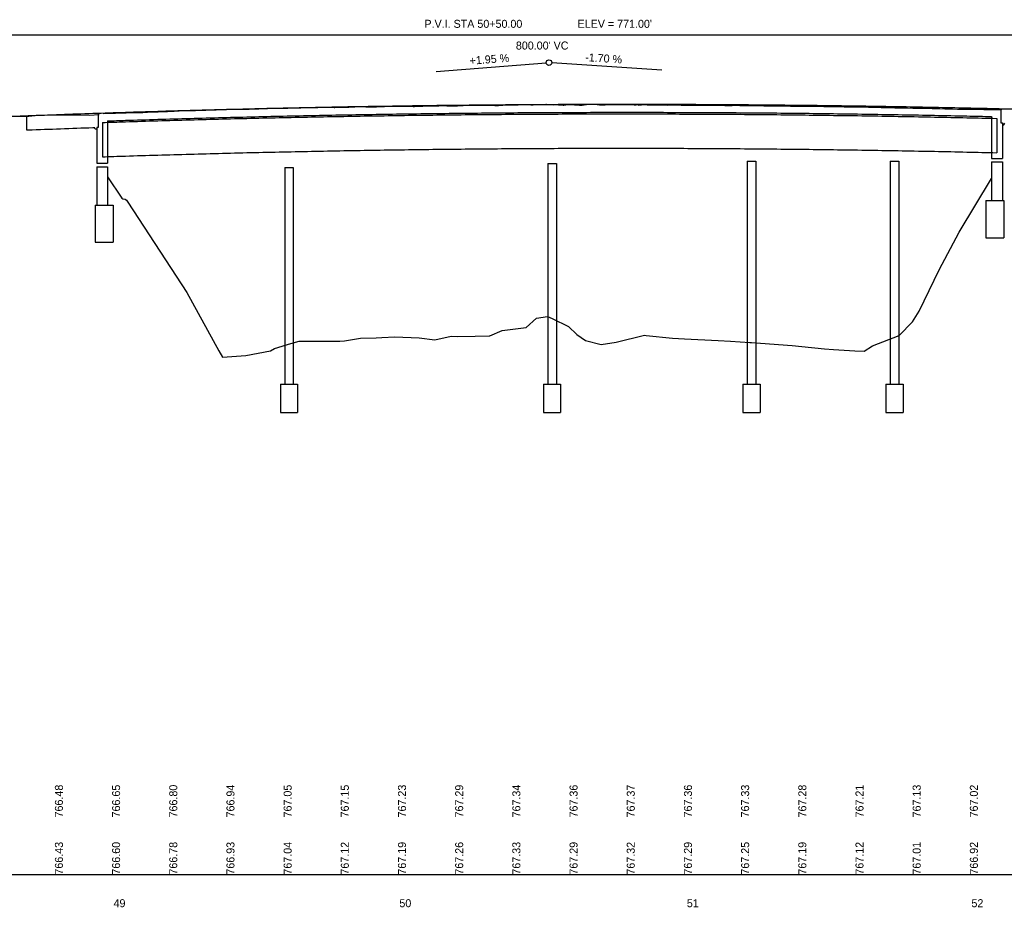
# Model space of a CAD drawing. Extents: x 40 to 3352, y -2509 to 347.
# Drawn here: x 317.3 to 661.7, y -1520 to -1209.6 of the extents above; entities that cross this region are included whole.
import ezdxf

# ---------------------------------------------------------------- set-up
doc = ezdxf.new("R2010")
doc.units = 0
for name, color, linetype in [('BR_P_Gen_Approach_Slab', 7, 'Continuous'), ('BR_P_Slab_Object', 7, 'Continuous'), ('BR_X_Sub_Object', 7, 'Continuous'), ('GK_Cells', 7, 'Continuous'), ('PF_P_Grade_Line', 7, 'Continuous'), ('PF_P_Sta_Elev_Text', 7, 'Continuous'), ('PF_P_Text', 7, 'Continuous'), ('PF_X_Ground_Line', 7, 'Continuous'), ('PF_X_Text', 7, 'Continuous'), ('XS_X_Ground_Line', 7, 'Continuous')]:
    doc.layers.add(name, color=color, linetype=linetype)

msp = doc.modelspace()

# ---------------------------------------------------------------- linework, layer by layer
at = {"layer": 'BR_P_Gen_Approach_Slab'}
for p, q in [((344.73, -1242.25), (344.73, -1247.25)), ((660.49, -1240.69), (660.49, -1245.69)), ((319.73, -1243.15), (319.73, -1248.15)), ((660.49, -1245.69), (660.99, -1245.69)), ((660.99, -1246.35), (661.49, -1246.35)), ((661.49, -1246.35), (661.81, -1245.72)), ((343.73, -1247.92), (343.42, -1247.3)), ((344.23, -1247.92), (343.73, -1247.92)), ((344.73, -1247.25), (344.23, -1247.25))]:
    msp.add_line(p, q, dxfattribs=at)
msp.add_spline([(319.73, -1248.15), (320.29, -1248.13), (331.61, -1247.71), (342.93, -1247.31), (343.42, -1247.3)], degree=3, dxfattribs=at)
at = {"layer": 'BR_P_Slab_Object'}
for p, q in [((347.99, -1244.98), (347.99, -1259.74)), ((657.23, -1243.44), (657.23, -1258.17)), ((660.99, -1245.69), (660.99, -1258.17)), ((344.23, -1247.25), (344.23, -1259.74)), ((344.23, -1259.74), (347.99, -1259.74)), ((657.23, -1258.17), (660.99, -1258.17))]:
    msp.add_line(p, q, dxfattribs=at)
at = {"layer": 'BR_X_Sub_Object'}
for p, q in [((346.23, -1245.53), (346.23, -1257.53)), ((658.99, -1244.1), (658.99, -1256.1)), ((501.98, -1259.82), (501.98, -1337.02)), ((501.98, -1259.82), (504.99, -1259.82)), ((504.99, -1259.82), (504.99, -1337.02)), ((571.73, -1259.1), (571.73, -1337.02)), ((571.73, -1259.1), (574.74, -1259.1)), ((574.74, -1259.1), (574.74, -1337.02)), ((621.73, -1259.06), (621.73, -1337.02)), ((621.73, -1259.06), (624.74, -1259.06)), ((624.74, -1259.06), (624.74, -1337.02)), ((657.23, -1259.33), (657.23, -1272.82)), ((657.23, -1259.33), (660.99, -1259.33)), ((660.99, -1259.33), (660.99, -1272.82)), ((344.23, -1261.08), (347.99, -1261.08)), ((344.23, -1261.08), (344.23, -1274.42)), ((347.99, -1261.08), (347.99, -1274.42)), ((409.98, -1261.22), (409.98, -1337.02)), ((409.98, -1261.22), (412.99, -1261.22)), ((412.99, -1261.22), (412.99, -1337.02)), ((655.23, -1272.82), (655.23, -1285.82)), ((655.23, -1272.82), (661.49, -1272.82)), ((661.49, -1272.82), (661.49, -1285.82)), ((343.73, -1274.42), (343.73, -1287.42)), ((343.73, -1274.42), (349.99, -1274.42)), ((349.99, -1274.42), (349.99, -1287.42)), ((343.73, -1287.42), (349.99, -1287.42)), ((655.23, -1285.82), (661.49, -1285.82)), ((408.48, -1337.02), (408.48, -1347.02)), ((408.48, -1337.02), (414.49, -1337.02)), ((414.49, -1337.02), (414.49, -1347.02)), ((500.48, -1337.02), (500.48, -1347.02)), ((500.48, -1337.02), (506.49, -1337.02)), ((506.49, -1337.02), (506.49, -1347.02)), ((570.23, -1337.02), (570.23, -1347.02)), ((570.23, -1337.02), (576.24, -1337.02)), ((576.24, -1337.02), (576.24, -1347.02)), ((620.23, -1337.02), (620.23, -1347.02)), ((620.23, -1337.02), (626.24, -1337.02)), ((626.24, -1337.02), (626.24, -1347.02)), ((408.48, -1347.02), (414.49, -1347.02)), ((500.48, -1347.02), (506.49, -1347.02)), ((570.23, -1347.02), (576.24, -1347.02)), ((620.23, -1347.02), (626.24, -1347.02))]:
    msp.add_line(p, q, dxfattribs=at)
for points in [[(346.23, -1245.53), (354.25, -1245.27), (365.57, -1244.92), (376.89, -1244.6), (388.21, -1244.3), (399.53, -1244.02), (410.85, -1243.77), (422.17, -1243.54), (433.49, -1243.33), (444.81, -1243.15), (456.13, -1242.99), (467.45, -1242.85), (478.77, -1242.74), (490.09, -1242.65), (501.41, -1242.59), (512.73, -1242.54), (524.05, -1242.52), (535.37, -1242.53), (546.69, -1242.56), (558.01, -1242.61), (569.33, -1242.68), (580.65, -1242.78), (591.97, -1242.9), (603.29, -1243.05), (614.61, -1243.21), (625.93, -1243.41), (637.25, -1243.62), (648.57, -1243.86), (658.99, -1244.1)], [(346.23, -1257.53), (354.25, -1257.27), (365.57, -1256.92), (376.89, -1256.6), (388.21, -1256.3), (399.53, -1256.02), (410.85, -1255.77), (422.17, -1255.54), (433.49, -1255.33), (444.81, -1255.15), (456.13, -1254.99), (467.45, -1254.85), (478.77, -1254.74), (490.09, -1254.65), (501.41, -1254.59), (512.73, -1254.54), (524.05, -1254.52), (535.37, -1254.53), (546.69, -1254.56), (558.01, -1254.61), (569.33, -1254.68), (580.65, -1254.78), (591.97, -1254.9), (603.29, -1255.05), (614.61, -1255.21), (625.93, -1255.41), (637.25, -1255.62), (648.57, -1255.86), (658.99, -1256.1)]]:
    msp.add_spline(points, degree=3, dxfattribs=at)
at = {"layer": 'GK_Cells'}
msp.add_line((52.42, -1508.6), (3352.42, -1508.6), dxfattribs=at)
at = {"layer": 'PF_P_Grade_Line'}
for points in [[(299.73, -1243.96), (308.97, -1243.58), (320.29, -1243.13), (331.61, -1242.71), (342.93, -1242.31), (354.25, -1241.94), (365.57, -1241.59), (376.89, -1241.26), (388.21, -1240.96), (399.53, -1240.68), (410.85, -1240.42), (422.17, -1240.18), (433.49, -1239.97), (444.81, -1239.79), (456.13, -1239.62), (467.45, -1239.48), (478.77, -1239.36), (490.09, -1239.27), (501.41, -1239.2), (512.73, -1239.15), (524.05, -1239.13), (535.37, -1239.13), (546.69, -1239.15), (558.01, -1239.2), (569.33, -1239.27), (580.65, -1239.36), (591.97, -1239.48), (603.29, -1239.62), (614.61, -1239.78), (625.93, -1239.97), (637.25, -1240.18), (648.57, -1240.41), (659.89, -1240.67), (671.21, -1240.95), (682.53, -1241.26), (693.85, -1241.58), (705.17, -1241.93), (705.49, -1241.94)], [(347.99, -1244.98), (354.25, -1244.77), (365.57, -1244.42), (376.89, -1244.09), (388.21, -1243.79), (399.53, -1243.51), (410.85, -1243.25), (422.17, -1243.02), (433.49, -1242.81), (444.81, -1242.62), (456.13, -1242.46), (467.45, -1242.32), (478.77, -1242.2), (490.09, -1242.1), (501.41, -1242.03), (512.73, -1241.99), (524.05, -1241.96), (535.37, -1241.96), (546.69, -1241.99), (558.01, -1242.03), (569.33, -1242.1), (580.65, -1242.2), (591.97, -1242.31), (603.29, -1242.45), (614.61, -1242.62), (625.93, -1242.8), (637.25, -1243.01), (648.57, -1243.25), (657.23, -1243.44)]]:
    msp.add_spline(points, degree=3, dxfattribs=at)
at = {"layer": 'PF_P_Text'}
for p, q in [((218.41, -1214.82), (784.41, -1214.82)), ((462.93, -1227.68), (501.42, -1224.67)), ((541.92, -1227.28), (503.41, -1224.66))]:
    msp.add_line(p, q, dxfattribs=at)
msp.add_circle((502.41, -1224.6), 1, dxfattribs=at)
at = {"layer": 'PF_X_Ground_Line'}
for points in [[(433.98, -1240.05), (434.53, -1240.03), (435.47, -1239.97), (436.16, -1239.96), (436.91, -1239.95), (438.35, -1240.05), (438.77, -1240.04), (439.72, -1240.03), (440.81, -1240.02), (442.06, -1240.01), (442.56, -1239.97), (443.1, -1239.94), (444.34, -1239.92), (444.86, -1239.91), (445.94, -1239.85), (446.34, -1239.83), (447.88, -1239.82), (448.24, -1239.82), (450.11, -1239.84), (450.27, -1239.83), (452.23, -1239.83), (452.27, -1239.83), (452.48, -1239.84), (454.89, -1239.93), (455.1, -1239.92), (455.35, -1239.91), (456.7, -1239.85), (457.89, -1239.78), (458.34, -1239.78), (459.52, -1239.73), (459.98, -1239.72), (461.31, -1239.7), (461.94, -1239.7), (463.1, -1239.67), (463.94, -1239.67), (464.72, -1239.62), (465.63, -1239.62), (466.69, -1239.74), (467.64, -1239.74), (468.57, -1239.7), (469.93, -1239.69), (470.39, -1239.66), (470.86, -1239.63), (472.02, -1239.6), (472.38, -1239.57), (473.59, -1239.53), (473.98, -1239.51), (475.64, -1239.51), (475.89, -1239.5), (477.65, -1239.49), (477.81, -1239.48), (480.05, -1239.51), (480.09, -1239.51), (483.48, -1239.63), (483.74, -1239.62), (484.81, -1239.54), (485.27, -1239.53), (486.28, -1239.46), (487.32, -1239.39), (487.73, -1239.38), (488.99, -1239.35), (489.73, -1239.36), (490.89, -1239.33), (491.61, -1239.32), (492.38, -1239.27), (492.98, -1239.21), (493.89, -1239.21), (494.76, -1239.19), (496.09, -1239.31), (496.89, -1239.3), (497.8, -1239.26), (499.4, -1239.27), (499.77, -1239.23), (500.19, -1239.21), (501.3, -1239.17), (501.53, -1239.14), (503.85, -1239.33), (503.9, -1239.34), (504.93, -1239.28), (505.77, -1239.36), (507.36, -1239.47), (507.6, -1239.51), (509.1, -1239.2), (509.6, -1239.19), (513.06, -1239.49), (513.68, -1239.49), (513.98, -1239.48), (516.26, -1239.09), (517.7, -1239.08), (519.23, -1239.2), (520.05, -1239.3), (520.44, -1239.35), (520.8, -1239.36), (522.02, -1239.32), (523.56, -1239.27), (524.48, -1239.23), (525.57, -1239.25), (526.72, -1239.28), (527.2, -1239.26), (528.4, -1239.25), (529.39, -1239.29)], [(433.98, -1240.05), (434.53, -1240.03), (435.47, -1239.97), (436.16, -1239.96), (436.91, -1239.95), (438.35, -1240.05), (438.77, -1240.04), (439.72, -1240.03), (440.81, -1240.02), (442.06, -1240.01), (442.56, -1239.97), (443.1, -1239.94), (444.34, -1239.92), (444.86, -1239.91), (445.94, -1239.85), (446.34, -1239.83), (447.88, -1239.82), (448.24, -1239.82), (450.11, -1239.84), (450.27, -1239.83), (452.23, -1239.83), (452.27, -1239.83), (452.48, -1239.84), (454.89, -1239.93), (455.1, -1239.92), (455.35, -1239.91), (456.7, -1239.85), (457.89, -1239.78), (458.34, -1239.78), (459.52, -1239.73), (459.98, -1239.72), (461.31, -1239.7), (461.94, -1239.7), (463.1, -1239.67), (463.94, -1239.67), (464.72, -1239.62), (465.63, -1239.62), (466.69, -1239.74), (467.64, -1239.74), (468.57, -1239.7), (469.93, -1239.69), (470.39, -1239.66), (470.86, -1239.63), (472.02, -1239.6), (472.38, -1239.57), (473.59, -1239.53), (473.98, -1239.51), (475.64, -1239.51), (475.89, -1239.5), (477.65, -1239.49), (477.81, -1239.48), (480.05, -1239.51), (480.09, -1239.51), (483.48, -1239.63), (483.74, -1239.62), (484.81, -1239.54), (485.27, -1239.53), (486.28, -1239.46), (487.32, -1239.39), (487.73, -1239.38), (488.99, -1239.35), (489.73, -1239.36), (490.89, -1239.33), (491.61, -1239.32), (492.38, -1239.27), (492.98, -1239.21), (493.89, -1239.21), (494.76, -1239.19), (496.09, -1239.31), (496.89, -1239.3), (497.8, -1239.26), (499.4, -1239.27), (499.77, -1239.23), (500.19, -1239.21), (501.3, -1239.17), (501.53, -1239.14), (503.85, -1239.33), (503.9, -1239.34), (504.93, -1239.28), (505.77, -1239.36), (507.36, -1239.47), (507.6, -1239.51), (509.1, -1239.2), (509.6, -1239.19), (513.06, -1239.49), (513.68, -1239.49), (513.98, -1239.48), (516.26, -1239.09), (517.7, -1239.08), (519.23, -1239.2), (520.05, -1239.3), (520.44, -1239.35), (520.8, -1239.36), (522.02, -1239.32), (523.56, -1239.27), (524.48, -1239.23), (525.57, -1239.25), (526.72, -1239.28), (527.2, -1239.26), (528.4, -1239.25), (529.39, -1239.29)], [(529.39, -1239.29), (530.16, -1239.21), (531.39, -1239.23), (532.1, -1239.29), (532.23, -1239.31), (532.88, -1239.32), (533.23, -1239.27), (533.82, -1239.43), (534.72, -1239.31), (535.44, -1239.26), (536.77, -1239.35), (536.98, -1239.37), (537.02, -1239.37), (537.9, -1239.31), (539.28, -1239.3), (540.16, -1239.3), (541.19, -1239.33), (542.27, -1239.36), (543.12, -1239.38), (543.9, -1239.49), (544.68, -1239.38), (545.28, -1239.34), (545.68, -1239.36), (547.27, -1239.37), (547.64, -1239.37), (548.69, -1239.51), (548.89, -1239.53), (549.27, -1239.52), (549.74, -1239.43), (552.1, -1239.45), (552.14, -1239.45), (552.18, -1239.45), (552.48, -1239.46), (553.77, -1239.45), (554.48, -1239.46), (555.36, -1239.46), (557.05, -1239.45), (557.85, -1239.46), (559.28, -1239.49), (559.52, -1239.47), (559.98, -1239.49), (561.65, -1239.5), (561.85, -1239.49), (562.39, -1239.5), (562.89, -1239.52), (563.89, -1239.54), (563.98, -1239.62), (564.18, -1239.61), (565.95, -1239.54), (566.32, -1239.55), (566.52, -1239.54), (567.28, -1239.52), (567.31, -1239.52), (567.56, -1239.53), (569.12, -1239.58), (569.91, -1239.59), (571.39, -1239.59), (572.78, -1239.59), (573.69, -1239.6), (575.18, -1239.63), (575.89, -1239.64), (577.09, -1239.6), (577.56, -1239.67), (578.03, -1239.69), (579.1, -1239.69), (579.97, -1239.69), (580.48, -1239.69), (581.88, -1239.66), (581.99, -1239.66), (582.81, -1239.71), (583.69, -1239.68), (584.53, -1239.7), (585.55, -1239.74), (586.82, -1239.77), (587.6, -1239.79), (589.23, -1239.8), (589.85, -1239.81), (591.68, -1239.81), (591.97, -1239.82), (592.12, -1239.82), (594.02, -1239.84), (594.27, -1239.84), (594.39, -1239.85), (596.35, -1239.87), (596.56, -1239.87), (598.53, -1239.89), (598.65, -1239.9), (598.85, -1239.89), (600.6, -1239.95), (600.98, -1239.96), (602.94, -1239.97), (603.27, -1239.98), (605.28, -1239.99), (605.6, -1240), (607.52, -1240.03), (607.85, -1240.03), (610.03, -1240.02), (610.28, -1240.02), (612.02, -1240.11), (612.32, -1240.11), (614.16, -1240.16)], [(529.39, -1239.29), (530.16, -1239.21), (531.39, -1239.23), (532.1, -1239.29), (532.23, -1239.31), (532.88, -1239.32), (533.23, -1239.27), (533.82, -1239.43), (534.72, -1239.31), (535.44, -1239.26), (536.77, -1239.35), (536.98, -1239.37), (537.02, -1239.37), (537.9, -1239.31), (539.28, -1239.3), (540.16, -1239.3), (541.19, -1239.33), (542.27, -1239.36), (543.12, -1239.38), (543.9, -1239.49), (544.68, -1239.38), (545.28, -1239.34), (545.68, -1239.36), (547.27, -1239.37), (547.64, -1239.37), (548.69, -1239.51), (548.89, -1239.53), (549.27, -1239.52), (549.74, -1239.43), (552.1, -1239.45), (552.14, -1239.45), (552.18, -1239.45), (552.48, -1239.46), (553.77, -1239.45), (554.48, -1239.46), (555.36, -1239.46), (557.05, -1239.45), (557.85, -1239.46), (559.28, -1239.49), (559.52, -1239.47), (559.98, -1239.49), (561.65, -1239.5), (561.85, -1239.49), (562.39, -1239.5), (562.89, -1239.52), (563.89, -1239.54), (563.98, -1239.62), (564.18, -1239.61), (565.95, -1239.54), (566.32, -1239.55), (566.52, -1239.54), (567.28, -1239.52), (567.31, -1239.52), (567.56, -1239.53), (569.12, -1239.58), (569.91, -1239.59), (571.39, -1239.59), (572.78, -1239.59), (573.69, -1239.6), (575.18, -1239.63), (575.89, -1239.64), (577.09, -1239.6), (577.56, -1239.67), (578.03, -1239.69), (579.1, -1239.69), (579.97, -1239.69), (580.48, -1239.69), (581.88, -1239.66), (581.99, -1239.66), (582.81, -1239.71), (583.69, -1239.68), (584.53, -1239.7), (585.55, -1239.74), (586.82, -1239.77), (587.6, -1239.79), (589.23, -1239.8), (589.85, -1239.81), (591.68, -1239.81), (591.97, -1239.82), (592.12, -1239.82), (594.02, -1239.84), (594.27, -1239.84), (594.39, -1239.85), (596.35, -1239.87), (596.56, -1239.87), (598.53, -1239.89), (598.65, -1239.9), (598.85, -1239.89), (600.6, -1239.95), (600.98, -1239.96), (602.94, -1239.97), (603.27, -1239.98), (605.28, -1239.99), (605.6, -1240), (607.52, -1240.03), (607.85, -1240.03), (610.03, -1240.02), (610.28, -1240.02), (612.02, -1240.11), (612.32, -1240.11), (614.16, -1240.16)], [(293.62, -1244.18), (294.33, -1244.19), (297.76, -1243.98), (300.36, -1243.89), (303, -1243.8), (304.55, -1243.81), (308.92, -1243.65), (313.31, -1243.49), (314.59, -1243.41), (319.01, -1243.35), (320.31, -1243.31), (320.45, -1243.3), (321.51, -1243.22), (323.87, -1242.99), (324.82, -1242.95), (326.99, -1242.89), (337.77, -1242.87), (341.71, -1242.92), (345.06, -1242.73)], [(345.1, -1242.31), (345.61, -1242.25)], [(346.48, -1242.34), (347.12, -1242.26), (348.43, -1242.27), (348.98, -1242.26), (350.43, -1242.25), (350.85, -1242.25), (352.35, -1242.18), (352.69, -1242.18), (354.32, -1242.15), (354.53, -1242.15), (356.26, -1242.09), (356.36, -1242.09), (358.09, -1242.06), (358.2, -1242.05), (360.09, -1242.05), (360.23, -1242.05), (360.4, -1242.04), (363.64, -1241.86), (363.89, -1241.85), (365.39, -1241.76), (365.7, -1241.75), (367.18, -1241.69), (367.57, -1241.68), (368.98, -1241.64), (370.01, -1241.61), (371.31, -1241.56), (372.47, -1241.49), (373.1, -1241.47), (374.52, -1241.39), (374.88, -1241.38), (375.64, -1241.36), (376.84, -1241.36), (377.85, -1241.37), (378.76, -1241.32), (379.74, -1241.28), (380.56, -1241.25), (381.27, -1241.2), (382.39, -1241.19), (383.02, -1241.16), (384.16, -1241.11), (384.76, -1241.09), (385.99, -1241.05), (386.48, -1241.04), (387.8, -1240.99), (388.21, -1240.98), (389.63, -1240.94), (389.94, -1240.93), (391.51, -1240.9), (391.73, -1240.9), (393.34, -1240.85), (394.81, -1240.85), (395.38, -1240.86), (395.43, -1240.86), (397.31, -1240.87), (397.51, -1240.87), (398.91, -1240.79), (399.16, -1240.78), (400.56, -1240.71), (400.89, -1240.7), (402.22, -1240.65), (402.64, -1240.64), (403.93, -1240.6), (404.39, -1240.58), (405.63, -1240.54), (406.26, -1240.54), (407.31, -1240.49), (407.99, -1240.47), (409.19, -1240.49), (410.05, -1240.47), (411.1, -1240.49), (412.06, -1240.46), (413.15, -1240.44), (413.85, -1240.41), (414.44, -1240.37), (415.63, -1240.36), (416.18, -1240.34), (417.49, -1240.32), (417.98, -1240.31), (419.47, -1240.3), (419.84, -1240.3), (421.27, -1240.25), (421.52, -1240.25), (423.19, -1240.23), (424.88, -1240.21), (425.18, -1240.21), (425.19, -1240.21), (427.28, -1240.25), (427.49, -1240.25), (428.9, -1240.19), (429.22, -1240.19), (430.61, -1240.15), (431.02, -1240.14), (432.39, -1240.12), (432.89, -1240.1), (433.98, -1240.05)], [(614.16, -1240.16), (614.49, -1240.17), (616.39, -1240.21), (616.72, -1240.22), (618.56, -1240.26), (618.9, -1240.27), (620.78, -1240.31), (621.11, -1240.32), (623.06, -1240.34), (623.4, -1240.35), (625.23, -1240.39), (625.61, -1240.4), (627.41, -1240.45), (627.81, -1240.46), (629.68, -1240.49), (630.06, -1240.5), (631.91, -1240.54), (632.31, -1240.54), (634.19, -1240.57), (634.56, -1240.58), (636.45, -1240.61), (636.85, -1240.61), (638.64, -1240.67), (639.05, -1240.68), (640.89, -1240.72), (641.31, -1240.72), (643.15, -1240.76), (643.56, -1240.77), (645.31, -1240.83), (645.77, -1240.84), (647.57, -1240.88), (648.05, -1240.88), (649.9, -1240.89), (650.35, -1240.91), (652.2, -1240.93), (652.65, -1240.93), (654.48, -1240.96), (654.93, -1240.97), (656.81, -1240.98), (656.87, -1240.98)], [(656.87, -1240.98), (660.68, -1240.96), (660.75, -1240.86), (663.2, -1240.75)]]:
    msp.add_lwpolyline(points, dxfattribs=at)
at = {"layer": 'XS_X_Ground_Line'}
msp.add_lwpolyline([(347.99, -1264.56), (353.02, -1272.01), (353.38, -1272.18), (354.14, -1272.37), (354.69, -1272.74), (355.17, -1273.43), (375.72, -1305.05), (386.89, -1325.44), (388.21, -1327.62), (396.39, -1327.05), (404.96, -1325.4), (406.38, -1324.53), (412.18, -1322.83), (415.07, -1321.99), (429.24, -1322.06), (430.93, -1321.87), (436.51, -1320.94), (441.94, -1320.85), (443.91, -1320.78), (448.54, -1320.48), (457.03, -1320.81), (462.49, -1321.51), (468.15, -1320.24), (470.48, -1320.4), (476.56, -1320.22), (481.46, -1320.11), (481.78, -1320.21), (486.04, -1318.3), (494.44, -1317.27), (498.1, -1313.98), (501.89, -1313.36), (503.48, -1314.13), (509.25, -1316.88), (512.18, -1319.73), (515.16, -1321.83), (520.68, -1323.21), (525.93, -1322.36), (535.81, -1319.92), (536.41, -1319.98), (545.61, -1320.95), (549.77, -1321.2), (561.58, -1321.76), (565.91, -1321.98), (572.65, -1322.43), (573.19, -1322.47), (587.42, -1323.54), (590.88, -1323.84), (598.82, -1324.66), (601.9, -1324.9), (609.43, -1325.4), (612.66, -1325.54), (615.51, -1323.67), (624.92, -1320.06), (629.55, -1315.23), (631.86, -1311.47), (638.86, -1297.12), (645.85, -1283.95), (657.23, -1265.13)], dxfattribs=at)

# ---------------------------------------------------------------- texts
at = {"layer": 'PF_P_Sta_Elev_Text'}
for s, p in [('49', (350.13, -1520)), ('49', (350.13, -1520)), ('50', (450.09, -1520)), ('50', (450.09, -1520)), ('51', (550.62, -1520)), ('51', (550.62, -1520)), ('52', (650.16, -1520)), ('52', (650.16, -1520))]:
    msp.add_text(s, height=2.8, dxfattribs=at).set_placement(p)
at = {"layer": 'PF_P_Text'}
for s, p in [('P.V.I. STA 50+50.00', (458.85, -1212.42)), ("ELEV = 771.00'", (512.41, -1212.42)), ("800.00' VC", (490.83, -1220.02))]:
    msp.add_text(s, height=2.8, dxfattribs=at).set_placement(p)
for s, rotation, p in [('+1.95 %', 4.46, (474.76, -1225.35)), ('-1.70 %', 356.1099, (515, -1224.05)), ('766.94', 90, (392.41, -1488.6)), ('767.34', 90, (492.41, -1488.6)), ('766.48', 90, (332.42, -1488.6)), ('766.65', 90, (352.41, -1488.6)), ('766.80', 90, (372.41, -1488.6)), ('767.05', 90, (412.41, -1488.6)), ('767.15', 90, (432.41, -1488.6)), ('767.23', 90, (452.41, -1488.6)), ('767.29', 90, (472.41, -1488.6)), ('767.36', 90, (512.41, -1488.6)), ('767.37', 90, (532.41, -1488.6)), ('767.36', 90, (552.41, -1488.6)), ('767.33', 90, (572.41, -1488.6)), ('767.28', 90, (592.41, -1488.6)), ('767.21', 90, (612.41, -1488.6)), ('767.13', 90, (632.41, -1488.6)), ('767.02', 90, (652.41, -1488.6))]:
    msp.add_text(s, height=2.8, rotation=rotation, dxfattribs=at).set_placement(p)
at = {"layer": 'PF_X_Text'}
for s, p in [('766.43', (332.42, -1508.6)), ('766.60', (352.41, -1508.6)), ('766.78', (372.41, -1508.6)), ('766.93', (392.41, -1508.6)), ('767.04', (412.41, -1508.6)), ('767.12', (432.41, -1508.6)), ('767.19', (452.41, -1508.6)), ('767.26', (472.41, -1508.6)), ('767.33', (492.41, -1508.6)), ('767.29', (512.41, -1508.6)), ('767.32', (532.41, -1508.6)), ('767.29', (552.41, -1508.6)), ('767.25', (572.41, -1508.6)), ('767.19', (592.41, -1508.6)), ('767.12', (612.41, -1508.6)), ('767.01', (632.41, -1508.6)), ('766.92', (652.41, -1508.6))]:
    msp.add_text(s, height=2.8, rotation=90, dxfattribs=at).set_placement(p)

doc.saveas('drawing.dxf')
